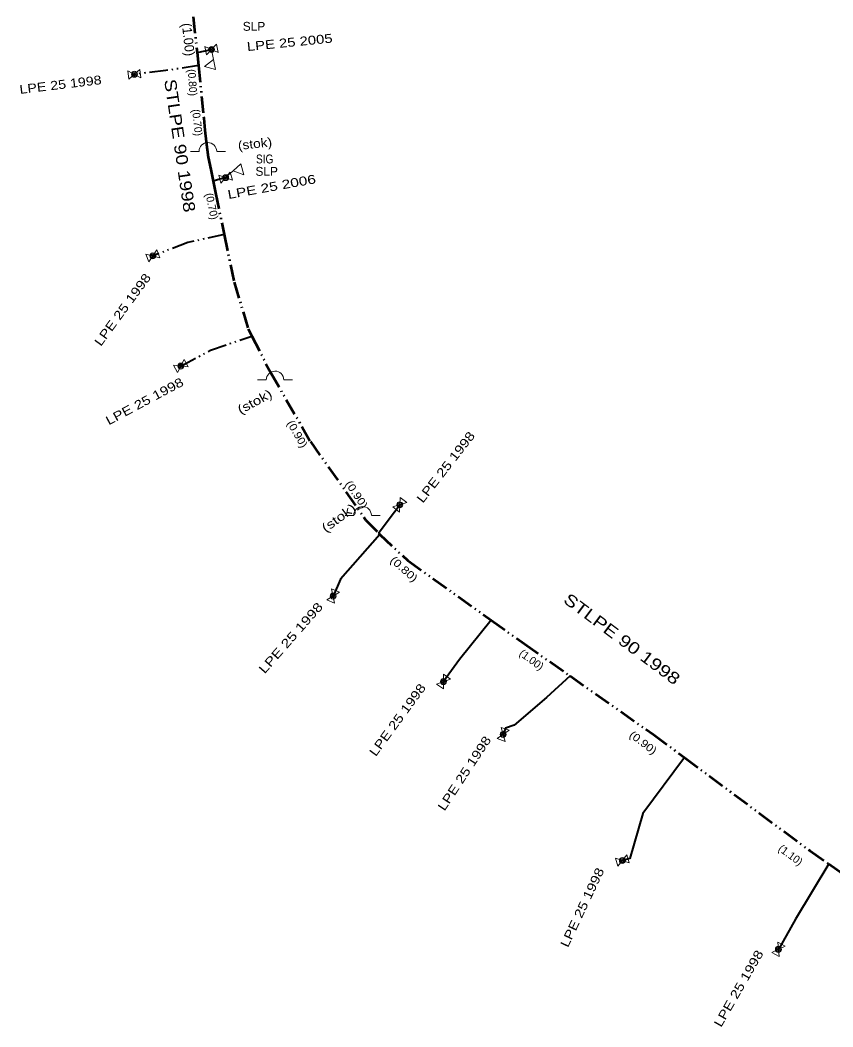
# Model space of a CAD drawing. Extents: x -648036 to -642998, y -1161549 to -1158141.
# Drawn here: x -644536.3 to -644467.8, y -1160115 to -1160030.1 of the extents above; entities that cross this region are included whole.
import ezdxf
from ezdxf.enums import TextEntityAlignment as Align

# ---------------------------------------------------------------- set-up
doc = ezdxf.new("R2010")
doc.units = 0
doc.header["$LTSCALE"] = 0.28
doc.linetypes.add('DASH_DOUBLE_DOT', pattern=[9.2, 5, -1.2, 0.3, -1.2, 0.3, -1.2])
for name, color, linetype, lineweight in [('12', 7, 'DASH_DOUBLE_DOT', 40), ('15', 7, 'Continuous', 13), ('19', 7, 'Continuous', 13), ('8', 7, 'Continuous', 53)]:
    doc.layers.add(name, color=color, linetype=linetype, lineweight=lineweight)
for name, color, linetype in [('20', 7, 'Continuous'), ('22', 7, 'Continuous'), ('27', 7, 'Continuous'), ('28', 7, 'Continuous'), ('35', 7, 'Continuous')]:
    doc.layers.add(name, color=color, linetype=linetype)

msp = doc.modelspace()

# ---------------------------------------------------------------- linework, layer by layer
at = {"layer": '12', "linetype": 'Continuous'}
for p, q in [((-644521.39, -1160032.82), (-644520.17, -1160032.57)), ((-644518.98, -1160043.38), (-644520.04, -1160043.67))]:
    msp.add_line(p, q, dxfattribs=at)
at = {"layer": '12'}
for points in [[(-644521.27, -1160033.93), (-644524.02, -1160034.35), (-644526.67, -1160034.66)], [(-644519.11, -1160048.17), (-644522.16, -1160048.86), (-644525.12, -1160049.98)], [(-644522.76, -1160059.27), (-644520.26, -1160057.94), (-644516.77, -1160056.75)]]:
    msp.add_lwpolyline(points, dxfattribs=at)
at = {"layer": '12', "linetype": 'Continuous'}
for points in [[(-644506.09, -1160073.37), (-644505.21, -1160072.15), (-644504.3, -1160070.97)], [(-644505.98, -1160073.47), (-644509.31, -1160077.26), (-644509.92, -1160078.67)], [(-644496.6, -1160080.7), (-644499.26, -1160084.01), (-644500.62, -1160085.89)], [(-644489.95, -1160085.41), (-644491.94, -1160087.24), (-644494.67, -1160089.55), (-644495.4, -1160089.82), (-644495.59, -1160090.34)], [(-644480.31, -1160092.29), (-644483.82, -1160097), (-644484.92, -1160100.8), (-644485.54, -1160100.98)], [(-644468.14, -1160101.26), (-644470.94, -1160105.93), (-644472.39, -1160108.47)]]:
    msp.add_lwpolyline(points, dxfattribs=at)
at = {"layer": '15'}
for p, q in [((-644520.734, -1160032.322), (-644520.592, -1160033.02)), ((-644519.605, -1160032.818), (-644520.734, -1160032.322)), ((-644519.748, -1160032.12), (-644520.592, -1160033.02)), ((-644519.748, -1160032.12), (-644519.605, -1160032.818)), ((-644520.17, -1160032.57), (-644519.998, -1160033.41)), ((-644527.212, -1160034.365), (-644526.129, -1160034.955)), ((-644527.129, -1160035.072), (-644527.212, -1160034.365)), ((-644527.129, -1160035.072), (-644526.211, -1160034.248)), ((-644526.129, -1160034.955), (-644526.211, -1160034.248)), ((-644521.955, -1160041.165), (-644521.22, -1160041.164)), ((-644519.734, -1160041.164), (-644519, -1160041.165)), ((-644519.559, -1160043.169), (-644519.372, -1160043.856)), ((-644518.4, -1160043.59), (-644519.559, -1160043.169)), ((-644518.588, -1160042.904), (-644519.372, -1160043.856)), ((-644518.98, -1160043.38), (-644518.346, -1160042.804)), ((-644518.588, -1160042.904), (-644518.4, -1160043.59)), ((-644525.717, -1160049.825), (-644524.524, -1160050.135)), ((-644525.465, -1160050.491), (-644525.717, -1160049.825)), ((-644525.465, -1160050.491), (-644524.775, -1160049.469)), ((-644524.524, -1160050.135), (-644524.775, -1160049.469)), ((-644523.372, -1160059.192), (-644522.149, -1160059.348)), ((-644523.038, -1160059.821), (-644523.372, -1160059.192)), ((-644523.038, -1160059.821), (-644522.482, -1160058.719)), ((-644522.149, -1160059.348), (-644522.482, -1160058.719)), ((-644516.295, -1160060.445), (-644515.56, -1160060.444)), ((-644514.074, -1160060.444), (-644513.34, -1160060.445)), ((-644504.274, -1160070.353), (-644504.326, -1160071.587)), ((-644504.274, -1160070.353), (-644503.71, -1160070.788)), ((-644503.71, -1160070.788), (-644504.889, -1160071.151)), ((-644504.889, -1160071.151), (-644504.326, -1160071.587)), ((-644508.915, -1160071.865), (-644508.18, -1160071.864)), ((-644506.694, -1160071.864), (-644505.96, -1160071.865)), ((-644509.394, -1160078.35), (-644510.047, -1160078.066)), ((-644509.793, -1160079.274), (-644510.047, -1160078.066)), ((-644510.447, -1160078.991), (-644509.394, -1160078.35)), ((-644509.793, -1160079.274), (-644510.447, -1160078.991)), ((-644501.204, -1160086.09), (-644500.037, -1160085.691)), ((-644500.627, -1160086.507), (-644500.613, -1160085.273)), ((-644500.037, -1160085.691), (-644500.613, -1160085.273)), ((-644500.627, -1160086.507), (-644501.204, -1160086.09)), ((-644496.097, -1160090.691), (-644495.083, -1160089.99)), ((-644495.083, -1160089.99), (-644495.751, -1160089.744)), ((-644495.429, -1160090.936), (-644495.751, -1160089.744)), ((-644495.429, -1160090.936), (-644496.097, -1160090.691)), ((-644486.123, -1160100.779), (-644484.958, -1160101.182)), ((-644485.925, -1160101.462), (-644486.123, -1160100.779)), ((-644485.925, -1160101.462), (-644485.155, -1160100.498)), ((-644484.958, -1160101.182), (-644485.155, -1160100.498)), ((-644471.831, -1160108.21), (-644472.449, -1160107.856)), ((-644472.331, -1160109.084), (-644472.449, -1160107.856)), ((-644472.949, -1160108.731), (-644471.831, -1160108.21)), ((-644472.331, -1160109.084), (-644472.949, -1160108.731))]:
    msp.add_line(p, q, dxfattribs=at)
for points in [[(-644519.998, -1160033.41), (-644520.75, -1160034.008), (-644519.823, -1160034.262)], [(-644518.346, -1160042.804), (-644517.447, -1160043.145), (-644517.702, -1160042.219)]]:
    msp.add_lwpolyline(points, close=True, dxfattribs=at)
for centre in [(-644520.4774, -1160041.1646), (-644514.8174, -1160060.4446), (-644507.4374, -1160071.8646)]:
    msp.add_arc(centre, 0.7431, 1.2748, 179.83951, dxfattribs=at)
at = {"layer": '19'}
for centre, radius in [((-644520.17, -1160032.57), 0.25), ((-644520.17, -1160032.57), 0.17), ((-644520.17, -1160032.57), 0.09), ((-644526.67, -1160034.66), 0.25), ((-644526.67, -1160034.66), 0.17), ((-644526.67, -1160034.66), 0.09), ((-644518.98, -1160043.38), 0.25), ((-644518.98, -1160043.38), 0.17), ((-644518.98, -1160043.38), 0.09), ((-644525.12, -1160049.98), 0.25), ((-644525.12, -1160049.98), 0.17), ((-644525.12, -1160049.98), 0.09), ((-644522.76, -1160059.27), 0.25), ((-644522.76, -1160059.27), 0.17), ((-644522.76, -1160059.27), 0.09), ((-644504.3, -1160070.97), 0.25), ((-644504.3, -1160070.97), 0.17), ((-644504.3, -1160070.97), 0.09), ((-644509.92, -1160078.67), 0.25), ((-644509.92, -1160078.67), 0.17), ((-644509.92, -1160078.67), 0.09), ((-644500.62, -1160085.89), 0.25), ((-644500.62, -1160085.89), 0.17), ((-644500.62, -1160085.89), 0.09), ((-644495.59, -1160090.34), 0.25), ((-644495.59, -1160090.34), 0.17), ((-644495.59, -1160090.34), 0.09), ((-644485.54, -1160100.98), 0.25), ((-644485.54, -1160100.98), 0.17), ((-644485.54, -1160100.98), 0.09), ((-644472.39, -1160108.47), 0.25), ((-644472.39, -1160108.47), 0.17), ((-644472.39, -1160108.47), 0.09)]:
    msp.add_circle(centre, radius, dxfattribs=at)
at = {"layer": '8', "linetype": 'DASH_DOUBLE_DOT'}
msp.add_line((-644519.84, -1160044.65), (-644519.11, -1160048.17), dxfattribs=at)
for points in [[(-644526.9, -1159990.37), (-644526.63, -1159991.44), (-644524.25, -1160005.98), (-644523.37, -1160013.75), (-644521.99, -1160027.22), (-644521.39, -1160032.82), (-644521.27, -1160033.93), (-644520.82, -1160038.37)], [(-644520.61, -1160040.36), (-644520.46, -1160041.65), (-644520.24, -1160042.69)], [(-644519.11, -1160048.17), (-644518.27, -1160052.2), (-644517.08, -1160056.12), (-644516.77, -1160056.75)], [(-644516.77, -1160056.75), (-644515.18, -1160059.85), (-644511.84, -1160065.63), (-644507.19, -1160072.23), (-644506.09, -1160073.37), (-644505.98, -1160073.47)], [(-644505.98, -1160073.47), (-644503.63, -1160075.68), (-644496.6, -1160080.7)], [(-644496.6, -1160080.7), (-644493.79, -1160082.7), (-644489.95, -1160085.41)], [(-644489.95, -1160085.41), (-644482.91, -1160090.36), (-644480.31, -1160092.29)], [(-644480.31, -1160092.29), (-644469.71, -1160100.17), (-644468.14, -1160101.26), (-644457.15, -1160109)]]:
    msp.add_lwpolyline(points, dxfattribs=at)
at = {"layer": '8'}
for points in [[(-644520.82, -1160038.37), (-644520.72, -1160039.37), (-644520.61, -1160040.36)], [(-644520.24, -1160042.69), (-644520.04, -1160043.67), (-644519.84, -1160044.65)]]:
    msp.add_lwpolyline(points, dxfattribs=at)

# ---------------------------------------------------------------- texts
at = {"layer": '15'}
for p in [(-644516.588, -1160030.991), (-644515.519, -1160043.224)]:
    msp.add_text('SLP', height=0.75, dxfattribs=at).set_placement(p, align=Align.CENTER)
at = {"layer": '15', "width": 0.85}
msp.add_text('SIG', height=0.75, dxfattribs=at).set_placement((-644515.6885, -1160042.18), align=Align.CENTER)
at = {"layer": '20'}
for rotation, width, p in [(278.458, 1.2, (-644523.3315, -1160040.75)), (323.148, 1.25, (-644485.8764, -1160082.6899))]:
    msp.add_text('STLPE 90 1998', height=1, rotation=rotation, dxfattribs=dict(at, width=width)).set_placement(p, align=Align.CENTER)
at = {"layer": '22'}
for s, rotation, width, p in [('LPE 25 2005', 5.73, 1.25, (-644513.5414, -1160032.3429)), ('LPE 25 1998', 6.875, 1.2, (-644532.8534, -1160035.9018)), ('LPE 25 2006', 10.313, 1.3, (-644515.0311, -1160044.5141)), ('LPE 25 1998', 53.858, 1.25, (-644527.3613, -1160054.7307)), ('LPE 25 1998', 28.075, 1.25, (-644525.6375, -1160062.5718)), ('LPE 25 1998', 52.139, 1.25, (-644500.1326, -1160068.0252)), ('LPE 25 1998', 48.701, 1.3, (-644513.2078, -1160082.4465)), ('LPE 25 1998', 53.858, 1.25, (-644504.1913, -1160089.3307)), ('LPE 25 1998', 56.723, 1.25, (-644498.5457, -1160093.8248)), ('LPE 25 1998', 64.744, 1.25, (-644488.5868, -1160105.091)), ('LPE 25 1998', 60.161, 1.25, (-644475.4173, -1160111.9531))]:
    msp.add_text(s, height=0.75, rotation=rotation, dxfattribs=dict(at, width=width)).set_placement(p, align=Align.CENTER)
at = {"layer": '27'}
for s, rotation, p in [('(0.80)', 273.874, (-644522.0967, -1160035.38)), ('(0.70)', 276.166, (-644521.6866, -1160038.7671)), ('(0.70)', 281.895, (-644520.4579, -1160045.859)), ('(1.00)', 323.721, (-644493.3913, -1160084.3023)), ('(1.10)', 323.721, (-644471.5518, -1160100.7684))]:
    msp.add_text(s, height=0.65, rotation=rotation, dxfattribs=at).set_placement(p, align=Align.CENTER)
for s, rotation, width, p in [('(0.90)', 300.23, 1.1, (-644513.217, -1160065.1629)), ('(0.90)', 303.668, 1.15, (-644508.2078, -1160070.2833)), ('(0.80)', 317.992, 1.2, (-644504.1635, -1160076.6339)), ('(0.90)', 322.575, 1.15, (-644483.985, -1160091.2878))]:
    msp.add_text(s, height=0.65, rotation=rotation, dxfattribs=dict(at, width=width)).set_placement(p, align=Align.CENTER)
at = {"layer": '28'}
for rotation, width, p in [(6.303, 1.15, (-644516.4692, -1160040.8892)), (28.648, 1.25, (-644516.3463, -1160062.6043)), (36.669, 1.3, (-644509.2319, -1160072.3785))]:
    msp.add_text('(stok)', height=0.75, rotation=rotation, dxfattribs=dict(at, width=width)).set_placement(p, align=Align.CENTER)
at = {"layer": '35'}
msp.add_text('(1.00)', height=0.8, rotation=276.166, dxfattribs=at).set_placement((-644522.5209, -1160031.771), align=Align.CENTER)

doc.saveas('drawing.dxf')
